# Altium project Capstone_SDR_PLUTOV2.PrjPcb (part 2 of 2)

## Sheet POWERMANAGE.SchDoc
size A3; SheetNumber: 10; SheetTotal: 13; SPICEModelCacheCHAYJENF: <root> / <DocumentId>CHAYJENF</DocumentId> / <CacheFrame Number="0"> / <Model Name="emk105bj105_v-f" Kind="CKT"> / <Text>* EMK105BJ105_V-F     SPICE MODEL  ( General Type ) / *-------------------------------------------------------------------------------------------------------- / * Model Generated by TAIYO YUDEN Corporation (http://www.ty-top.com) / * Version 1.0 / * TAIYO YUDEN Control No. 170508_130520 / * Copyright(c) 2012 TAIYO YUDEN CO.,LTD. All Rights Reserved. / *-------------------------------------------------------------------------------------------------------- / * / * Products Name : Multilayer Ceramic Capacitors / * / * Characteristics : / *     Capacitance : 1 uF , Rated Voltage : 16V , TCC : X5R / *     Case Size : 1.0 x 0.5 / 0.039 x 0.02 [mm/inch] , Thickness : 0.5 / 0.02 [mm/inch] / *     (Conditions: Temperature = 25 degC , DC Bias Current/Voltage = 0A / 0V) / * / * Frequency Range : 40Hz - 3GHz / * / * External Node Assignments : / * / *  1  o---¦ ¦---o  2 / * / *-------------------------------------------------------------------------------------------------------- / .SubCkt EMK105BJ105_V-F 1 2 / **************************** / C0 1 110 0.68309u / Cm 1 101 0.26053u / C1 101 102 0.94076u / Rc1 101 102 1.9029k / C2 102 103 0.66707u / Rc2 102 103 120.36 / C3 103 110 0.57203u / Rc3 103 110 2.1097 / C2m 1 301 0.1871u / C21 301 302 3.2494u / Rc21 301 302 1.1117k / C22 302 303 2.1014u / Rc22 302 303 1.484k / C23 303 304 2.1172u / Rc23 303 304 1.3876k / C24 304 305 0.75729u / Rc24 304 305 332.59 / C25 305 306 0.94401u / Rc25 305 306 249.09 / C26 306 307 0.34674u / Rc26 306 307 28.352 / C27 307 308 0.37158u / Rc27 307 308 19.989 / C28 308 309 0.17933u / Rc28 308 309 31.748 / C29 309 110 0.016445u / Rc29 309 110 1.0592 / Rp0 1 110 100Meg / L0 110 120 0.2216n / Lm 120 130 0.1509n / L1 120 121 0.12659n / RL1 121 130 0.85161 / L2 120 122 0.15996n / RL2 122 130 0.42469 / L3 120 123 7.9543n / RL3 123 130 0.54643m / CR 120 124 0.24334u / LR 124 125 0.090738n / RR 125 130 68.076m / CL 130 140 2.7354p / LL 130 140 0.10762n / RL 130 140 50.614 / Rs 140 2 7.5416m / **************************** / .ends EMK105BJ105_V-F</Text> / </Model> / </CacheFrame> / </root>
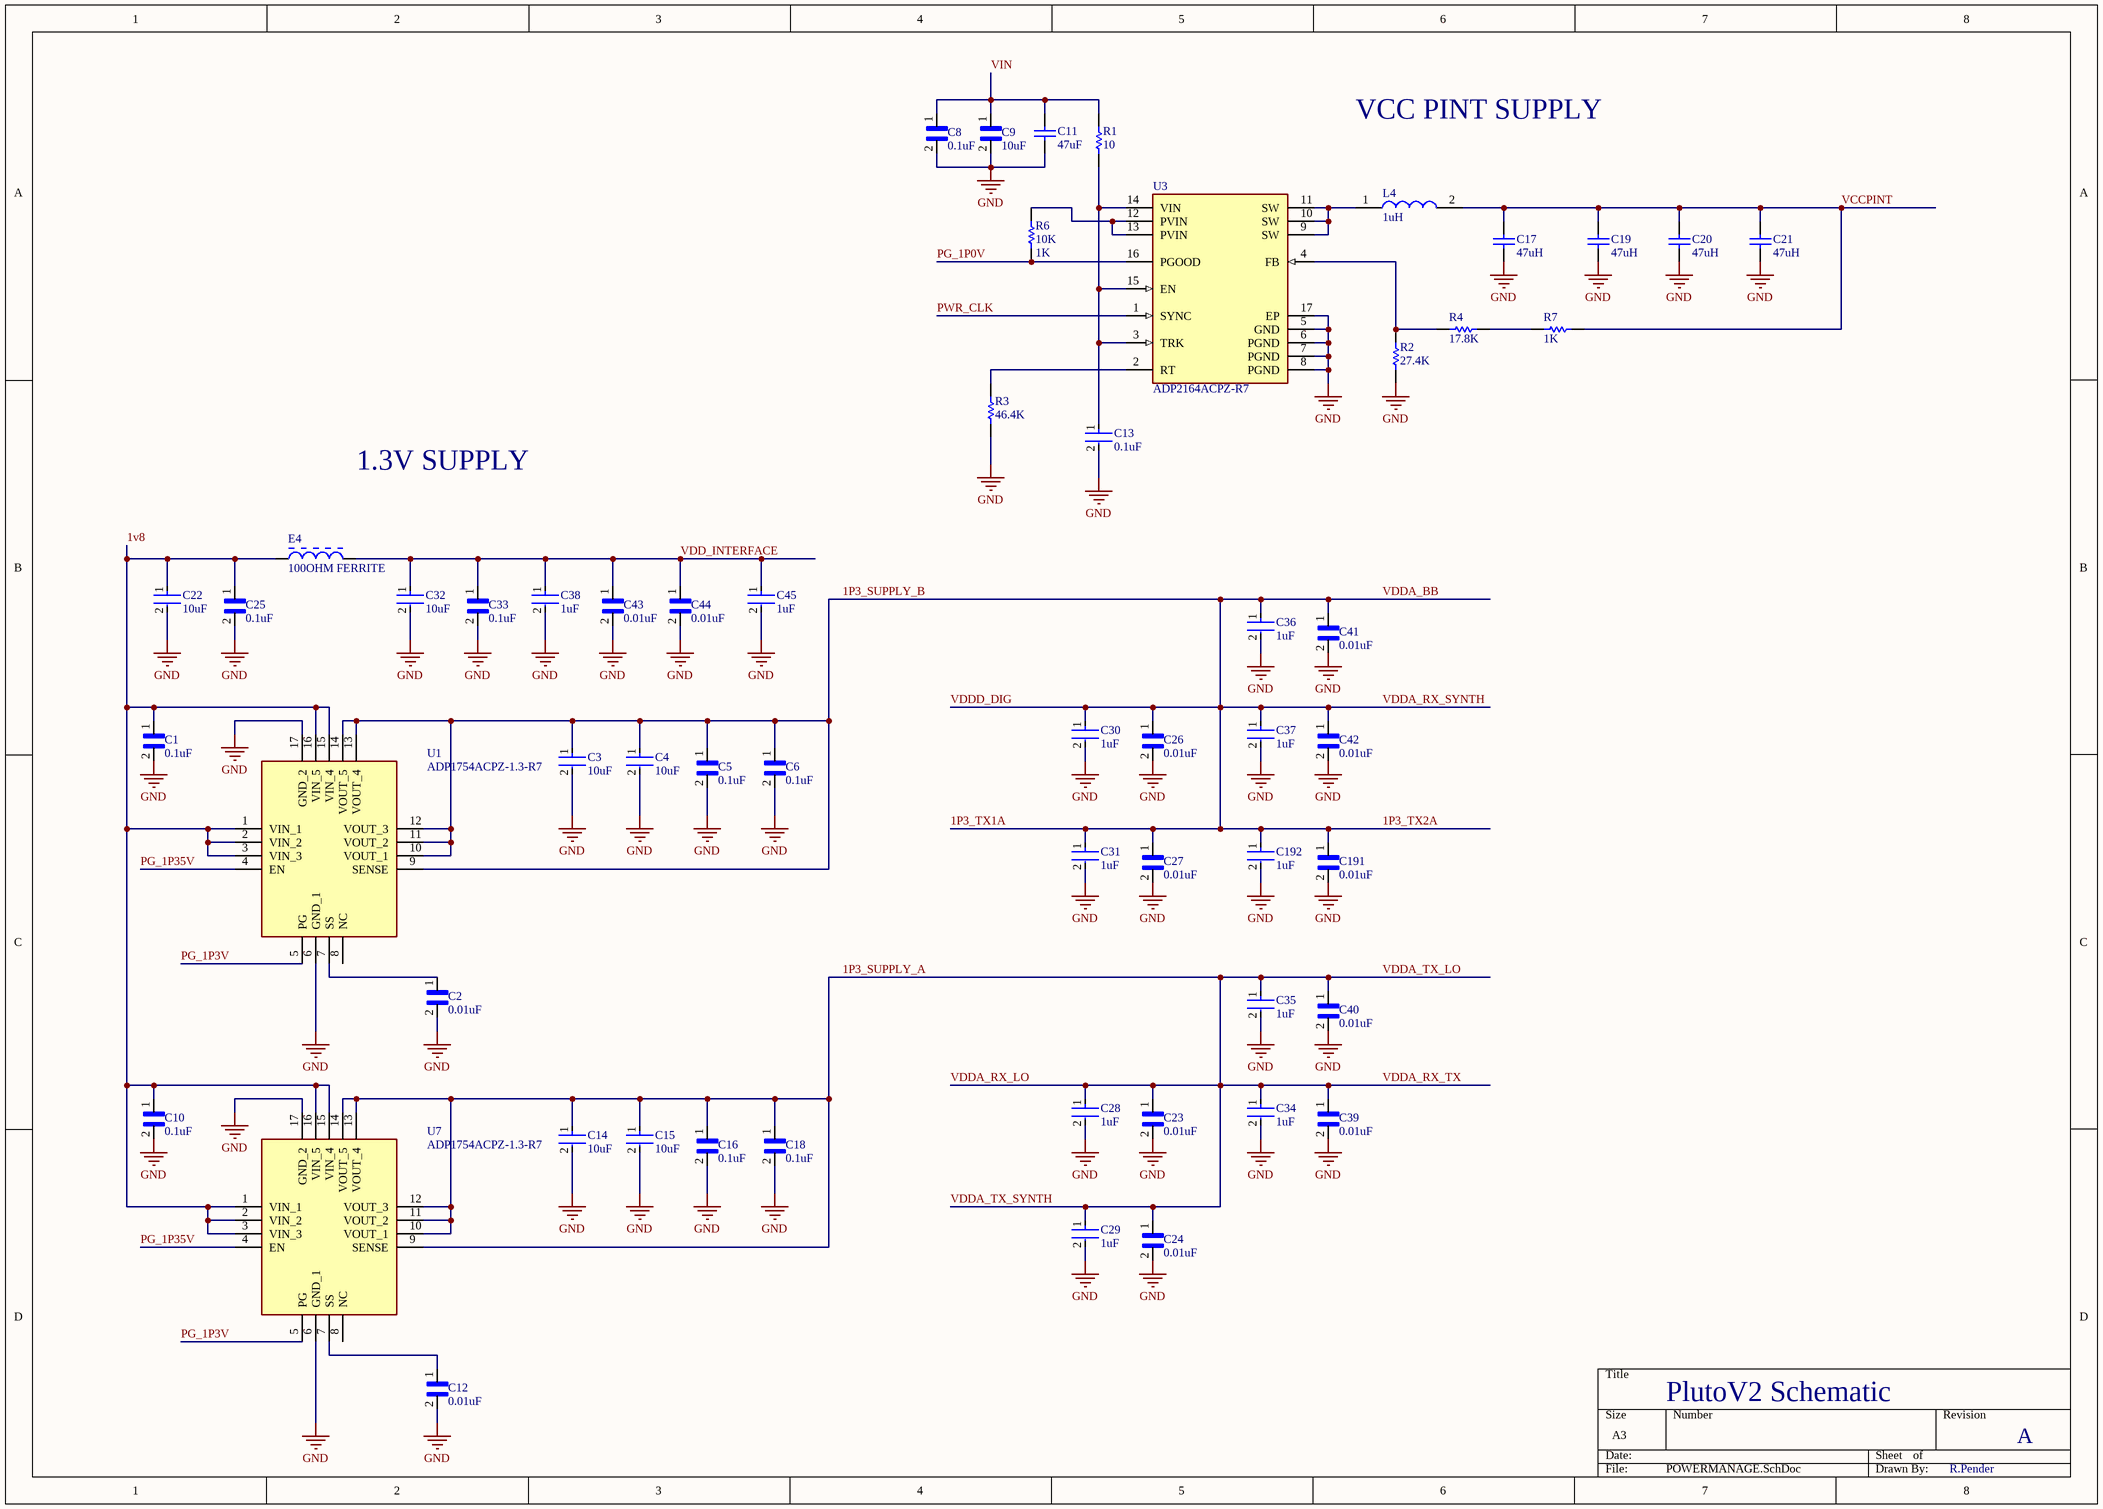
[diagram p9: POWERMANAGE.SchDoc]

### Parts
C1  0.1uF  [CAPC0603X33N]
C2  0.01uF  [CAPC0603X33N]
C3  10uF  [FP-GRM188-0_1-e0_2_0_55-IPC_C]
C4  10uF  [FP-GRM188-0_1-e0_2_0_55-IPC_C]
C5  0.1uF  [CAPC0603X33N]
C6  0.1uF  [CAPC0603X33N]
C8  0.1uF  [CAPC0603X33N]
C9  10uF  [CAPC0603X33N]
C10  0.1uF  [CAPC0603X33N]
C11  47uF  [TAYO-JMK212BBJ476MG-T_L]
C12  0.01uF  [CAPC0603X33N]
C13  0.1uF  [FP-GRM188-0_15-MFG]
C14  10uF  [FP-GRM188-0_1-e0_2_0_55-IPC_C]
C15  10uF  [FP-GRM188-0_1-e0_2_0_55-IPC_C]
C16  0.1uF  [CAPC0603X33N]
C17  47uH  [TAYO-JMK212BBJ476MG-T_L]
C18  0.1uF  [CAPC0603X33N]
C19  47uH  [TAYO-JMK212BBJ476MG-T_L]
C20  47uH  [TAYO-JMK212BBJ476MG-T_L]
C21  47uH  [TAYO-JMK212BBJ476MG-T_L]
C22  10uF  [FP-GRM188-0_1-e0_2_0_55-IPC_C]
C23  0.01uF  [CAPC0603X33N]
C24  0.01uF  [CAPC0603X33N]
C25  0.1uF  [CAPC0603X33N]
C26  0.01uF  [CAPC0603X33N]
C27  0.01uF  [CAPC0603X33N]
C28  1uF  [FP-0402-L_1_0_0_05-W_0_5-IPC_B]
C29  1uF  [FP-0402-L_1_0_0_05-W_0_5-IPC_B]
C30  1uF  [FP-0402-L_1_0_0_05-W_0_5-IPC_B]
C31  1uF  [FP-0402-L_1_0_0_05-W_0_5-IPC_B]
C32  10uF  [FP-GRM188-0_1-e0_2_0_55-IPC_C]
C33  0.1uF  [CAPC0603X33N]
C34  1uF  [FP-0402-L_1_0_0_05-W_0_5-IPC_B]
C35  1uF  [FP-0402-L_1_0_0_05-W_0_5-IPC_B]
C36  1uF  [FP-0402-L_1_0_0_05-W_0_5-IPC_B]
C37  1uF  [FP-0402-L_1_0_0_05-W_0_5-IPC_B]
C38  1uF  [FP-0402-L_1_0_0_05-W_0_5-IPC_A]
C39  0.01uF  [CAPC0603X33N]
C40  0.01uF  [CAPC0603X33N]
C41  0.01uF  [CAPC0603X33N]
C42  0.01uF  [CAPC0603X33N]
C43  0.01uF  [CAPC0603X33N]
C44  0.01uF  [CAPC0603X33N]
C45  1uF  [FP-0402-L_1_0_0_05-W_0_5-IPC_A]
C191  0.01uF  [CAPC0603X33N]
C192  1uF  [FP-0402-L_1_0_0_05-W_0_5-IPC_B]
E4  100OHM FERRITE  [TDK-MPZ2012S101A-2_V]
L4  1uH  [XFL4020102MEB]
R1  10  [RESC0603X26X15LL03T05]
R2  27.4K  [2-0402]
R3  46.4K  [1-0201]
R4  17.8K  [2-0402]
R6  10K  value 1K  [RESC1005X35N]
R7  1K  [2-0402]
U1  ADP1754ACPZ-1.3-R7  [QFN65P400X400X80-17N-D]
U3  ADP2164ACPZ-R7  [FP-CP-16-26-IPC_C]
U7  ADP1754ACPZ-1.3-R7  [QFN65P400X400X80-17N-D]

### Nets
GND: C1.2 C2.2 C3.2 C4.2 C5.2 C6.2 C8.2 C9.2 C10.2 C11.2 C12.2 C13.2 C14.2 C15.2 C16.2 C17.2 C18.2 C19.2 C20.2 C21.2 C22.2 C23.2 C24.2 C25.2 C26.2 C27.2 C28.2 C29.2 C30.2 C31.2 C32.2 C33.2 C34.2 C35.2 C36.2 C37.2 C38.2 C39.2 C40.2 C41.2 C42.2 C43.2 C44.2 C45.2 C191.2 C192.2 R2.2 R3.2 U1.6(GND_1) U1.17(GND_2) U3.5(GND) U3.6(PGND) U3.7(PGND) U3.8(PGND) U3.17(EP) U7.6(GND_1) U7.17(GND_2)
1P3_SUPPLY_A: C14.1 C15.1 C16.1 C18.1 C23.1 C24.1 C28.1 C29.1 C34.1 C35.1 C39.1 C40.1 U7.9(SENSE) U7.10(VOUT_1) U7.11(VOUT_2) U7.12(VOUT_3) U7.13(VOUT_4) U7.14(VOUT_5)  [also labelled VDDA_RX_LO, VDDA_RX_TX, VDDA_TX_LO, VDDA_TX_SYNTH]
1P3_SUPPLY_B: C3.1 C4.1 C5.1 C6.1 C26.1 C27.1 C30.1 C31.1 C36.1 C37.1 C41.1 C42.1 C191.1 C192.1 U1.9(SENSE) U1.10(VOUT_1) U1.11(VOUT_2) U1.12(VOUT_3) U1.13(VOUT_4) U1.14(VOUT_5)  [also labelled 1P3_TX1A, 1P3_TX2A, VDDA_BB, VDDA_RX_SYNTH, VDDD_DIG]
1v8: C1.1 C10.1 C22.1 C25.1 E4.1 U1.1(VIN_1) U1.2(VIN_2) U1.3(VIN_3) U1.15(VIN_4) U1.16(VIN_5) U7.1(VIN_1) U7.2(VIN_2) U7.3(VIN_3) U7.15(VIN_4) U7.16(VIN_5)
PG_1P0V: R6.1 U3.16(PGOOD)
PG_1P3V: U1.5(PG) U7.5(PG)
PG_1P35V: U1.4(EN) U7.4(EN)
PWR_CLK: U3.1(SYNC)
VCCPINT: C17.1 C19.1 C20.1 C21.1 L4.2 R7.2
VDD_INTERFACE: C32.1 C33.1 C38.1 C43.1 C44.1 C45.1 E4.2
VIN: C8.1 C9.1 C11.1 R1.2
NetC2_1: C2.1 U1.7(SS)
NetC12_1: C12.1 U7.7(SS)
NetC13_1: C13.1 R1.1 U3.3(TRK) U3.14(VIN) U3.15(EN)
NetL4_1: L4.1 U3.9(SW) U3.10(SW) U3.11(SW)
NetR2_1: R2.1 R4.1 U3.4(FB)
NetR3_1: R3.1 U3.2(RT)
NetR4_2: R4.2 R7.1
NetR6_2: R6.2 U3.12(PVIN) U3.13(PVIN)

Not connected (* = marked no-connect by the designer): U1 8(NC); U7 8(NC)

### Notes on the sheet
- VCC PINT SUPPLY
- 1.3V SUPPLY
- PlutoV2 Schematic
- A
- R.Pender

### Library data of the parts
C1 C5 C6 C8 C10 C16 C18 C25 C33 = GRM033R61C104ME84D: CAP 0.1UF 16VDC X5R 20% SMD 0201 PAPER TAPE
C2 C9 C12 C23 C24 C26 C27 C39-C44 C191 = GRM033R71A103KA01D: SMD Capacitor X7R(EIA) with Capacitance: 10000pF Tol. 10%. Rated Voltage: 10Vdc; MF: Murata
C3 C4 C14 C15 C22 C32 = CMP-2006-02792-2: Chip Multilayer Ceramic Capacitors for General Purpose, 0603, 10uF, X5R, 15%, 20%, 6.3V
C11 C17 C19-C21 = CMP-2000-06498-1: High Value Multilayer Ceramic Capacitor, 47 uF, +/-20%, 6.3 V, -55 to 85 degC, 2-Pin SMD (0805), RoHS, Tape and Reel; Manufacturer: Taiyo Yuden; PCN Part Number: X5R,X7RDielectrics23/Jan/2008; Kits: 587-1797-KIT-ND-KITCAPCERHICAP0603&0805S; Temperature Coefficient: X5R; Tolerance: ±20%; Online Catalog: MSeries; Other Names: 587-1779-1; Capacitance: 47µF; Voltage - Rated: 6.3V; Catalog Drawings: xMKSeries_0805_1.25
C13 = CMP-06035-003612-1: Chip Multilayer Ceramic Capacitors for General Purpose, 0603, 10uF, X5R, 15%, 20%, 10V
C28-C31 C34-C38 C45 C192 = CMP-14477-000104-2: None; Tolerance: 10%; Voltage Rating: 16V; Dielectric: X5R
E4 = CMP-2000-05399-1: Chip Bead for Power Line, 100 Ohm, +/- 25%, 4 A, -55 to 125 degC, 0805 (2012 Metric), RoHS, Tape and Reel; Manufacturer: TDK; Maximum DC Resistance: 20mOhms; Test Frequency: 100MHz; Impedance: 100Ohms; Case Width: 1.25mm; Case Length: 2mm; Maximum DC Current: 4A; Case Height: 0.85mm
L4 = XFL4020-102MEB: Inductor; Manufacturer_Name: COILCRAFT
R1 = CMP-2004-03448-1: Manufacturer: Panasonic; Part Number: ERJ1GNF10R0C
R2 R4 R7 = ERJ2RK: Precision Thick Film Chip Resistor, 10 Ohm to 1M Ohm Range, 1% and 0.5% Tolerance, 0402 Size, 0.063 W
R3 = ERJ1GE: Thick Film Chip Resistor, 10 Ohm to 1M Ohm Range, 5% Tolerance, 0201 Size, 0.05 W; Note: If flow soldering, adjust pad width of PCB Footprint to 0.7 - 0.8 times the width of the resistor.
R6 = Res1: Resistor
U1 U7 = ADP1754ACPZ-1.3-R7: Integrated Circuit; Manufacturer_Name: Analog Devices
U3 = CMP-09139-000017-1: IC REG BUCK ADJ 4A 16LFCSP; Manufacturer: Analog Devices; Standoff Height: 0.02mm; Max Junction Temp: +125°C; Description: Buck Switching Regulator IC Positive Adjustable 0.6V 1 Output 4A 16-WQFN Exposed Pad, CSP; Max Duty Cycle: 100%; Output Type: AdjustableProgrammable; Switching Frequency: 500-1400kHz; Min Supply Voltage: 2.7V; Max Supply Voltage: 6.5V; Nominal Supply Current: 895uA; Number Of Outputs: 1; Output Voltage: 0.6-6.5V

## Sheet POWERMANAGE2.SchDoc
size A3; SheetNumber: 11; SheetTotal: 13; SPICEModelCacheVRZJBZTH: <root> / <DocumentId>VRZJBZTH</DocumentId> / <CacheFrame Number="0"> / <Model Name="emk105bj105_v-f" Kind="CKT"> / <Text>* EMK105BJ105_V-F     SPICE MODEL  ( General Type ) / *-------------------------------------------------------------------------------------------------------- / * Model Generated by TAIYO YUDEN Corporation (http://www.ty-top.com) / * Version 1.0 / * TAIYO YUDEN Control No. 170508_130520 / * Copyright(c) 2012 TAIYO YUDEN CO.,LTD. All Rights Reserved. / *-------------------------------------------------------------------------------------------------------- / * / * Products Name : Multilayer Ceramic Capacitors / * / * Characteristics : / *     Capacitance : 1 uF , Rated Voltage : 16V , TCC : X5R / *     Case Size : 1.0 x 0.5 / 0.039 x 0.02 [mm/inch] , Thickness : 0.5 / 0.02 [mm/inch] / *     (Conditions: Temperature = 25 degC , DC Bias Current/Voltage = 0A / 0V) / * / * Frequency Range : 40Hz - 3GHz / * / * External Node Assignments : / * / *  1  o---¦ ¦---o  2 / * / *-------------------------------------------------------------------------------------------------------- / .SubCkt EMK105BJ105_V-F 1 2 / **************************** / C0 1 110 0.68309u / Cm 1 101 0.26053u / C1 101 102 0.94076u / Rc1 101 102 1.9029k / C2 102 103 0.66707u / Rc2 102 103 120.36 / C3 103 110 0.57203u / Rc3 103 110 2.1097 / C2m 1 301 0.1871u / C21 301 302 3.2494u / Rc21 301 302 1.1117k / C22 302 303 2.1014u / Rc22 302 303 1.484k / C23 303 304 2.1172u / Rc23 303 304 1.3876k / C24 304 305 0.75729u / Rc24 304 305 332.59 / C25 305 306 0.94401u / Rc25 305 306 249.09 / C26 306 307 0.34674u / Rc26 306 307 28.352 / C27 307 308 0.37158u / Rc27 307 308 19.989 / C28 308 309 0.17933u / Rc28 308 309 31.748 / C29 309 110 0.016445u / Rc29 309 110 1.0592 / Rp0 1 110 100Meg / L0 110 120 0.2216n / Lm 120 130 0.1509n / L1 120 121 0.12659n / RL1 121 130 0.85161 / L2 120 122 0.15996n / RL2 122 130 0.42469 / L3 120 123 7.9543n / RL3 123 130 0.54643m / CR 120 124 0.24334u / LR 124 125 0.090738n / RR 125 130 68.076m / CL 130 140 2.7354p / LL 130 140 0.10762n / RL 130 140 50.614 / Rs 140 2 7.5416m / **************************** / .ends EMK105BJ105_V-F</Text> / </Model> / </CacheFrame> / </root>
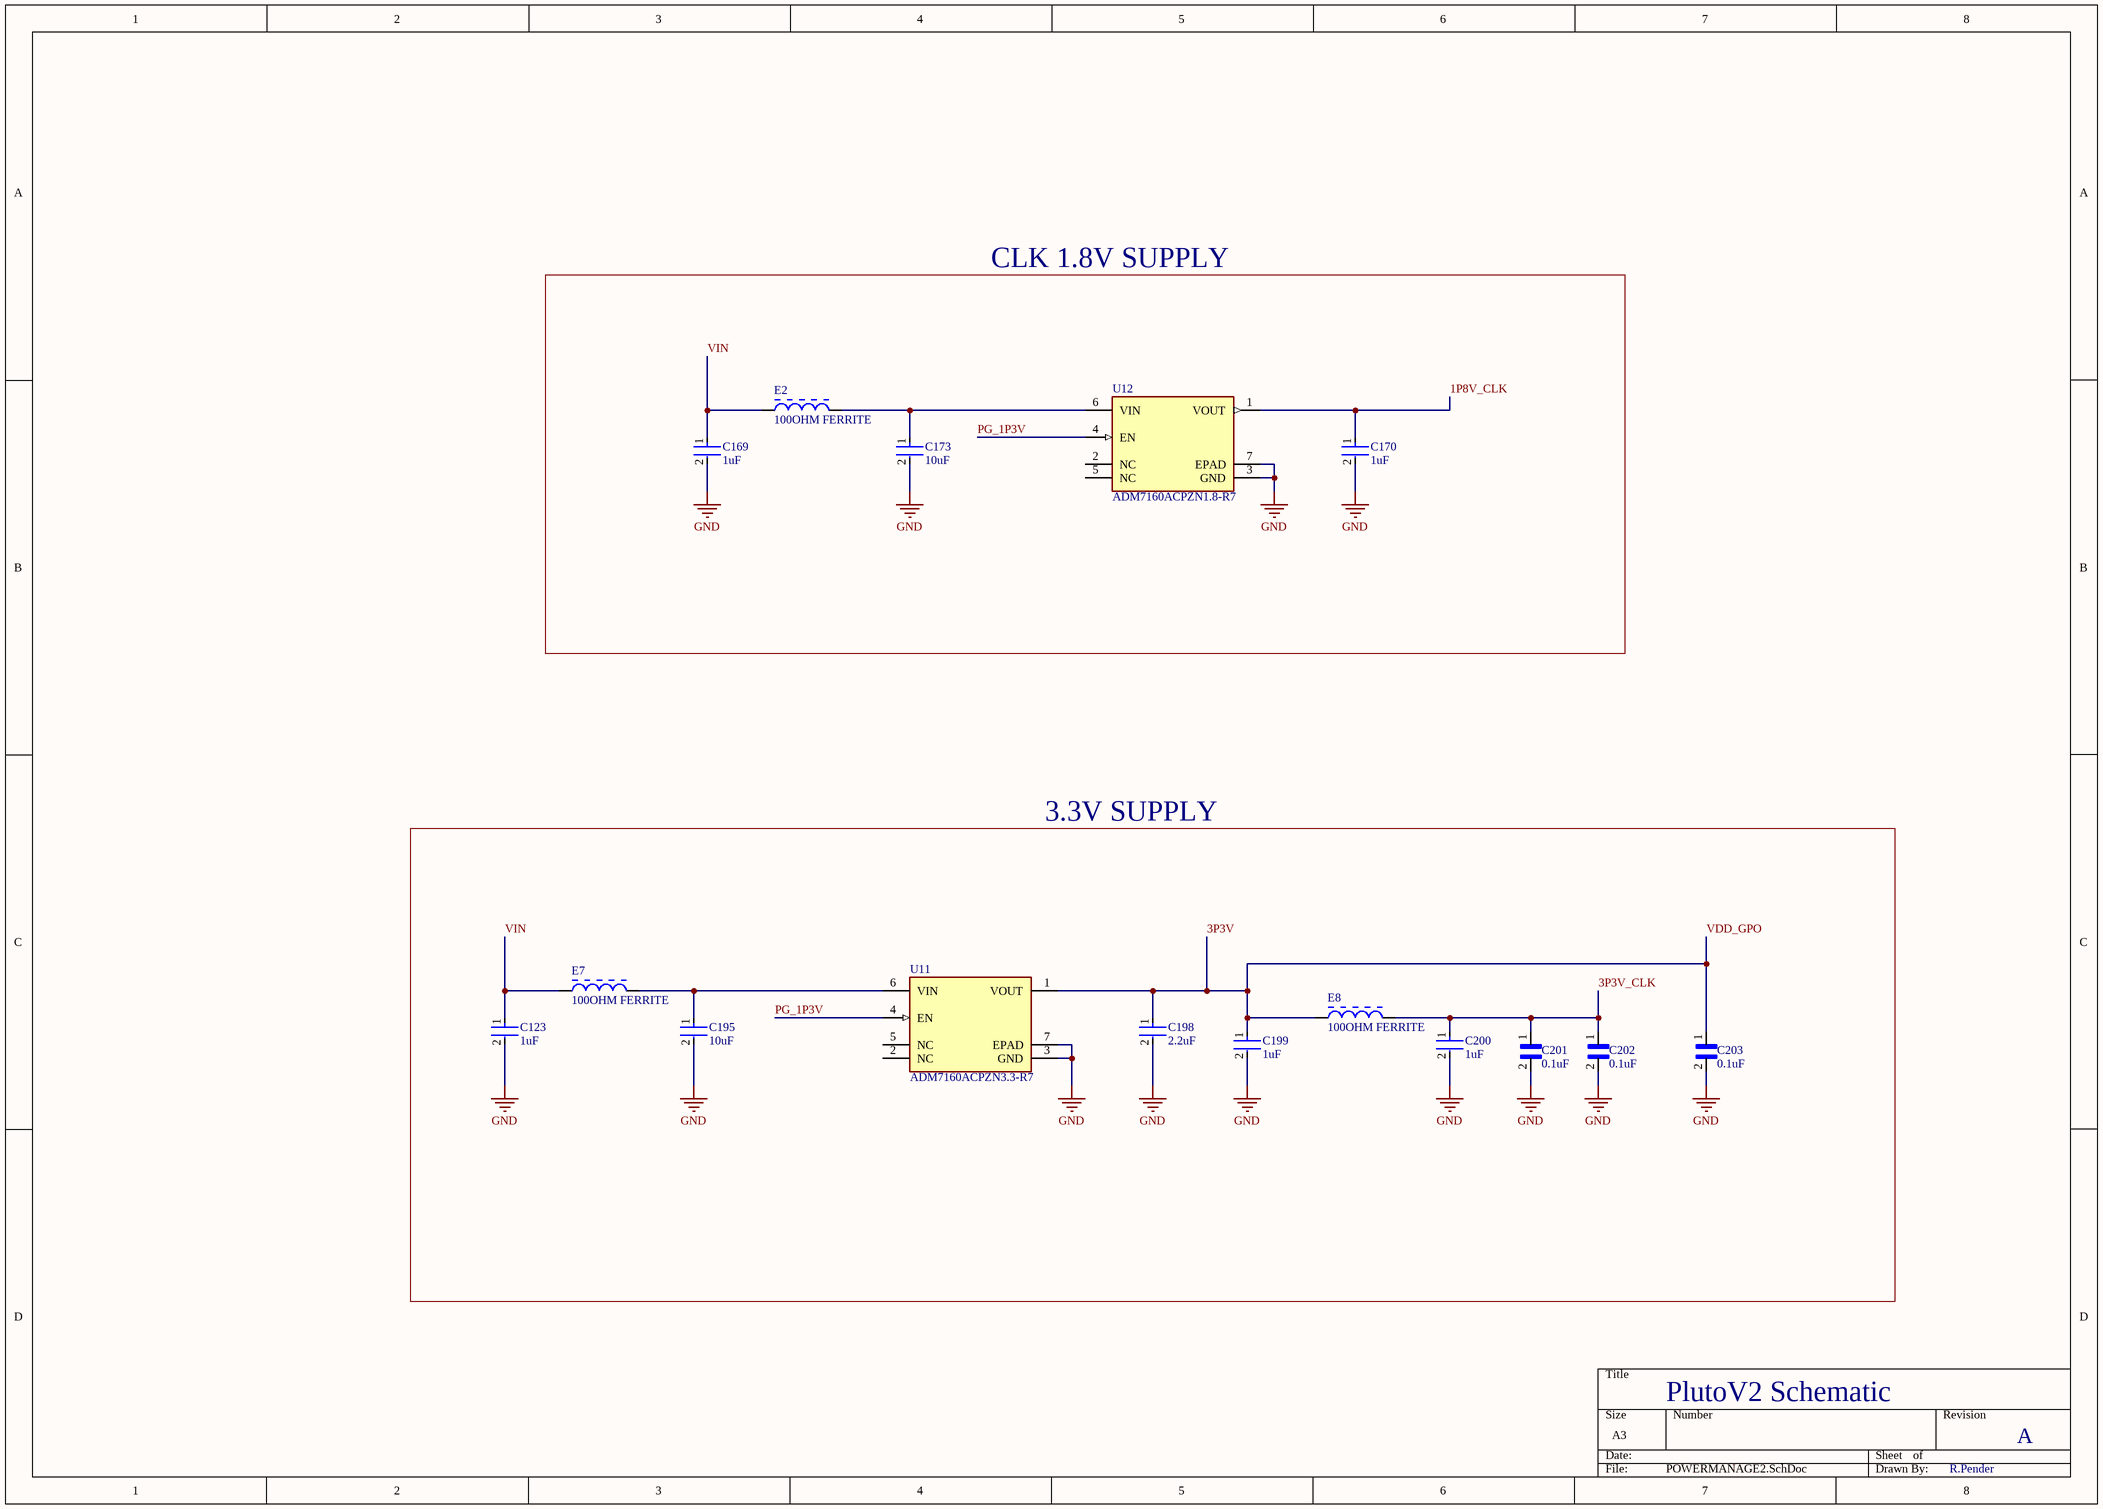
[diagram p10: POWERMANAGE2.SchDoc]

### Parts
C123  1uF  [FP-0402-L_1_0_0_05-W_0_5-IPC_A]
C169  1uF  [FP-0402-L_1_0_0_05-W_0_5-IPC_A]
C170  1uF  [FP-0402-L_1_0_0_05-W_0_5-IPC_B]
C173  10uF  [FP-GRM188-0_15-MFG]
C195  10uF  [FP-GRM188-0_15-MFG]
C198  2.2uF  [FP-GRM188-0_2-MFG]
C199  1uF  [FP-0402-L_1_0_0_05-W_0_5-IPC_A]
C200  1uF  [FP-0402-L_1_0_0_05-W_0_5-IPC_A]
C201  0.1uF  [CAPC0603X33N]
C202  0.1uF  [CAPC0603X33N]
C203  0.1uF  [CAPC0603X33N]
E2  100OHM FERRITE  [TDK-MPZ2012S101A-2_V]
E7  100OHM FERRITE  [TDK-MPZ2012S101A-2_V]
E8  100OHM FERRITE  [TDK-MPZ2012S101A-2_V]
U11  ADM7160ACPZN3.3-R7  [FP-CP-6-3-IPC_A]
U12  ADM7160ACPZN1.8-R7  [FP-CP-6-3-IPC_C]

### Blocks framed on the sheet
CLK 1.8V SUPPLY: C169 C170 C173 E2 U12
3.3V SUPPLY: C123 C195 C198-C203 E7 E8 U11

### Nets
GND: C123.2 C169.2 C170.2 C173.2 C195.2 C198.2 C199.2 C200.2 C201.2 C202.2 C203.2 U11.3(GND) U11.7(EPAD) U12.3(GND) U12.7(EPAD)
1P8V_CLK: C170.1 U12.1(VOUT)
3P3V: C198.1 C199.1 C203.1 E8.1 U11.1(VOUT)  [also labelled VDD_GPO]
3P3V_CLK: C200.1 C201.1 C202.1 E8.2
PG_1P3V: U11.4(EN) U12.4(EN)
VIN: C123.1 C169.1 E2.1 E7.1
NetC173_1: C173.1 E2.2 U12.6(VIN)
NetC195_1: C195.1 E7.2 U11.6(VIN)

Not connected (* = marked no-connect by the designer): U11 2(NC) 5(NC); U12 2(NC) 5(NC)

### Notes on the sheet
- PlutoV2 Schematic
- A
- R.Pender

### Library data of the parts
C123 C169 C170 C199 C200 = CMP-14477-000104-2: as C28-C31 on sheet POWERMANAGE
C173 C195 = CMP-06035-003612-1: as C13 on sheet POWERMANAGE
C198 = CMP-06035-023692-1: Chip Multilayer Ceramic Capacitors for General Purpose, 0603, 2.2uF, X5R, 15%, 10%, 50V
C201-C203 = GRM033R61C104ME84D: as C1 on sheet POWERMANAGE
E2 E7 E8 = CMP-2000-05399-1: as E4 on sheet POWERMANAGE
U11 = CMP-09138-000129-1: IC REG LINEAR 3.3V 200MA 6LFCSP; Output Type: Fixed; Max Supply Current: 265uA; Max Input Voltage: 5.5V; Number of Regulators: 1; Power Supply Rejection Ratio (PSRR): 49dB; Operating Supply Current: 265mA; Polarity: Positive; Min Input Voltage: 2.2V; Dropout Voltage: 150mV; Accuracy: 1%; Min Current Limit: 220mA
U12 = CMP-09138-000112-1: IC REG LINEAR 1.8V 200MA 6LFCSP; Operating Supply Current: 265mA; Power Supply Rejection Ratio (PSRR): 49dB; Polarity: Positive; Max Supply Current: 265uA; Dropout Voltage: 230mV; Number of Outputs: 1; Min Current Limit: 220mA; Output Type: Fixed; Accuracy: 1%; Min Input Voltage: 2.2V; Max Input Voltage: 5.5V

## Sheet TESTPOINTS.SchDoc
size A3; SheetNumber: 12; SheetTotal: 13
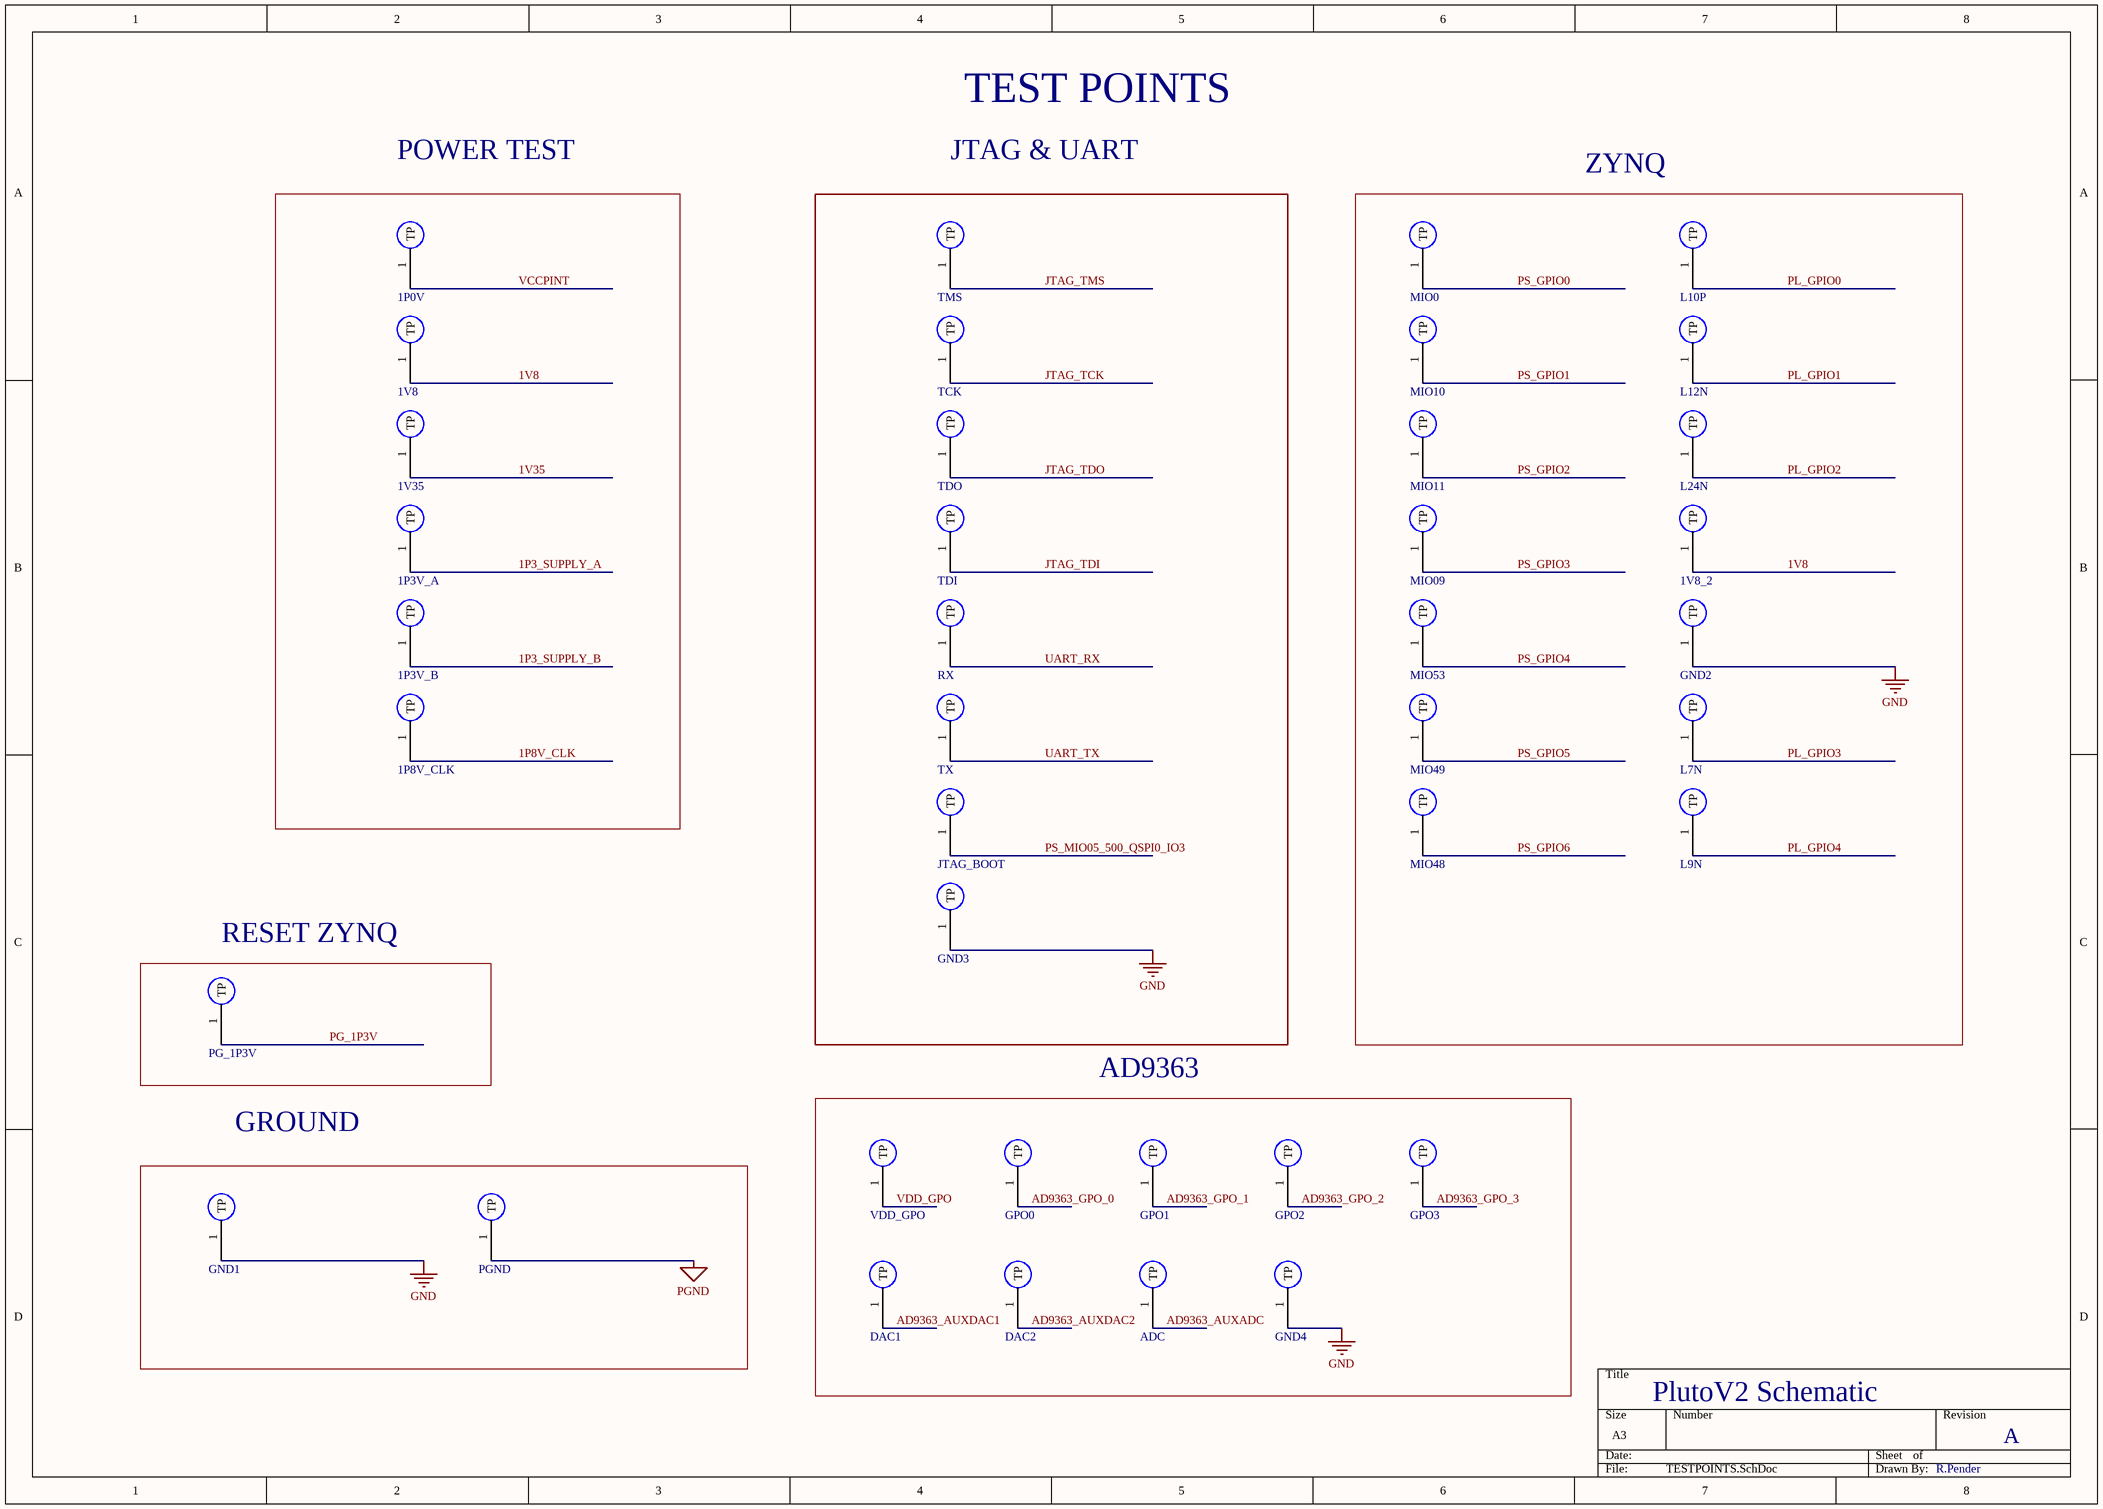
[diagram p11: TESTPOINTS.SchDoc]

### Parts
1P0V  TEST POINT  [TESTPOINT1]  (value not drawn)  (no BOM)
1P3V_A  TEST POINT  [TESTPOINT1]  (value not drawn)  (no BOM)
1P3V_B  TEST POINT  [TESTPOINT1]  (value not drawn)  (no BOM)
1P8V_CLK  TEST POINT  [TESTPOINT1]  (value not drawn)  (no BOM)
1V8  TEST POINT  [TESTPOINT1]  (value not drawn)  (no BOM)
1V8_2  TEST POINT  [TESTPOINT1]  (value not drawn)  (no BOM)
1V35  TEST POINT  [TESTPOINT1]  (value not drawn)  (no BOM)
ADC  TEST POINT  [TESTPOINT1]  (value not drawn)  (no BOM)
DAC1  TEST POINT  [TESTPOINT1]  (value not drawn)  (no BOM)
DAC2  TEST POINT  [TESTPOINT1]  (value not drawn)  (no BOM)
GND1  TEST POINT  [TESTPOINT1]  (value not drawn)  (no BOM)
GND2  TEST POINT  [TESTPOINT1]  (value not drawn)  (no BOM)
GND3  TEST POINT  [TESTPOINT1]  (value not drawn)  (no BOM)
GND4  TEST POINT  [TESTPOINT1]  (value not drawn)  (no BOM)
GPO0  TEST POINT  [TESTPOINT1]  (value not drawn)  (no BOM)
GPO1  TEST POINT  [TESTPOINT1]  (value not drawn)  (no BOM)
GPO2  TEST POINT  [TESTPOINT1]  (value not drawn)  (no BOM)
GPO3  TEST POINT  [TESTPOINT1]  (value not drawn)  (no BOM)
JTAG_BOOT  TEST POINT  [TESTPOINT1]  (value not drawn)  (no BOM)
L7N  TEST POINT  [TESTPOINT1]  (value not drawn)  (no BOM)
L9N  TEST POINT  [TESTPOINT1]  (value not drawn)  (no BOM)
L10P  TEST POINT  [TESTPOINT1]  (value not drawn)  (no BOM)
L12N  TEST POINT  [TESTPOINT1]  (value not drawn)  (no BOM)
L24N  TEST POINT  [TESTPOINT1]  (value not drawn)  (no BOM)
MIO0  TEST POINT  [TESTPOINT1]  (value not drawn)  (no BOM)
MIO09  TEST POINT  [TESTPOINT1]  (value not drawn)  (no BOM)
MIO10  TEST POINT  [TESTPOINT1]  (value not drawn)  (no BOM)
MIO11  TEST POINT  [TESTPOINT1]  (value not drawn)  (no BOM)
MIO48  TEST POINT  [TESTPOINT1]  (value not drawn)  (no BOM)
MIO49  TEST POINT  [TESTPOINT1]  (value not drawn)  (no BOM)
MIO53  TEST POINT  [TESTPOINT1]  (value not drawn)  (no BOM)
PG_1P3V  TEST POINT  [TESTPOINT1]  (value not drawn)  (no BOM)
PGND  TEST POINT  [TESTPOINT1]  (value not drawn)  (no BOM)
RX  TEST POINT  [TESTPOINT1]  (value not drawn)  (no BOM)
TCK  TEST POINT  [TESTPOINT1]  (value not drawn)  (no BOM)
TDI  TEST POINT  [TESTPOINT1]  (value not drawn)  (no BOM)
TDO  TEST POINT  [TESTPOINT1]  (value not drawn)  (no BOM)
TMS  TEST POINT  [TESTPOINT1]  (value not drawn)  (no BOM)
TX  TEST POINT  [TESTPOINT1]  (value not drawn)  (no BOM)
VDD_GPO  TEST POINT  [TESTPOINT1]  (value not drawn)  (no BOM)

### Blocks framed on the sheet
ZYNQ: 1V8_2 GND2 L7N L9N L10P L12N L24N MIO0 MIO09-MIO11 MIO48 MIO49 MIO53
RESET ZYNQ: PG_1P3V
AD9363: ADC DAC1 DAC2 GND4 GPO0-GPO3 VDD_GPO

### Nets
GND: GND1.1(TP) GND2.1(TP) GND3.1(TP) GND4.1(TP)
PGND: PGND.1(TP)
1P3_SUPPLY_A: 1P3V_A.1(TP)
1P3_SUPPLY_B: 1P3V_B.1(TP)
1P8V_CLK: 1P8V_CLK.1(TP)
1v8: 1V8.1(TP) 1V8_2.1(TP)
1v35: 1V35.1(TP)
AD9363_AUXADC: ADC.1(TP)
AD9363_AUXDAC1: DAC1.1(TP)
AD9363_AUXDAC2: DAC2.1(TP)
AD9363_GPO_0: GPO0.1(TP)
AD9363_GPO_1: GPO1.1(TP)
AD9363_GPO_2: GPO2.1(TP)
AD9363_GPO_3: GPO3.1(TP)
JTAG_TCK: TCK.1(TP)
JTAG_TDI: TDI.1(TP)
JTAG_TDO: TDO.1(TP)
JTAG_TMS: TMS.1(TP)
PG_1P3V: PG_1P3V.1(TP)
PL_GPIO0: L10P.1(TP)
PL_GPIO1: L12N.1(TP)
PL_GPIO2: L24N.1(TP)
PL_GPIO3: L7N.1(TP)
PL_GPIO4: L9N.1(TP)
PS_GPIO0: MIO0.1(TP)
PS_GPIO1: MIO10.1(TP)
PS_GPIO2: MIO11.1(TP)
PS_GPIO3: MIO09.1(TP)
PS_GPIO4: MIO53.1(TP)
PS_GPIO5: MIO49.1(TP)
PS_GPIO6: MIO48.1(TP)
PS_MIO05_500_QSPI0_IO3: JTAG_BOOT.1(TP)
UART_RX: RX.1(TP)
UART_TX: TX.1(TP)
VCCPINT: 1P0V.1(TP)
VDD_GPO: VDD_GPO.1(TP)  [project net 3P3V]

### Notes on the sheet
- TEST POINTS
- POWER TEST
- JTAG & UART
- GROUND
- PlutoV2 Schematic
- A
- R.Pender

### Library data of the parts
1P0V 1P3V_A 1P3V_B 1P8V_CLK 1V8 1V8_2 1V35 ADC DAC1 DAC2 GND1-GND4 GPO0-GPO3 JTAG_BOOT L7N L9N L10P L12N L24N MIO0 MIO09-MIO11 MIO48 MIO49 MIO53 PG_1P3V PGND RX TCK TDI TDO TMS TX VDD_GPO = TESTPT

## Sheet AD9363 OSCILLATORS.SchDoc
size A3; SheetNumber: 13; SheetTotal: 13
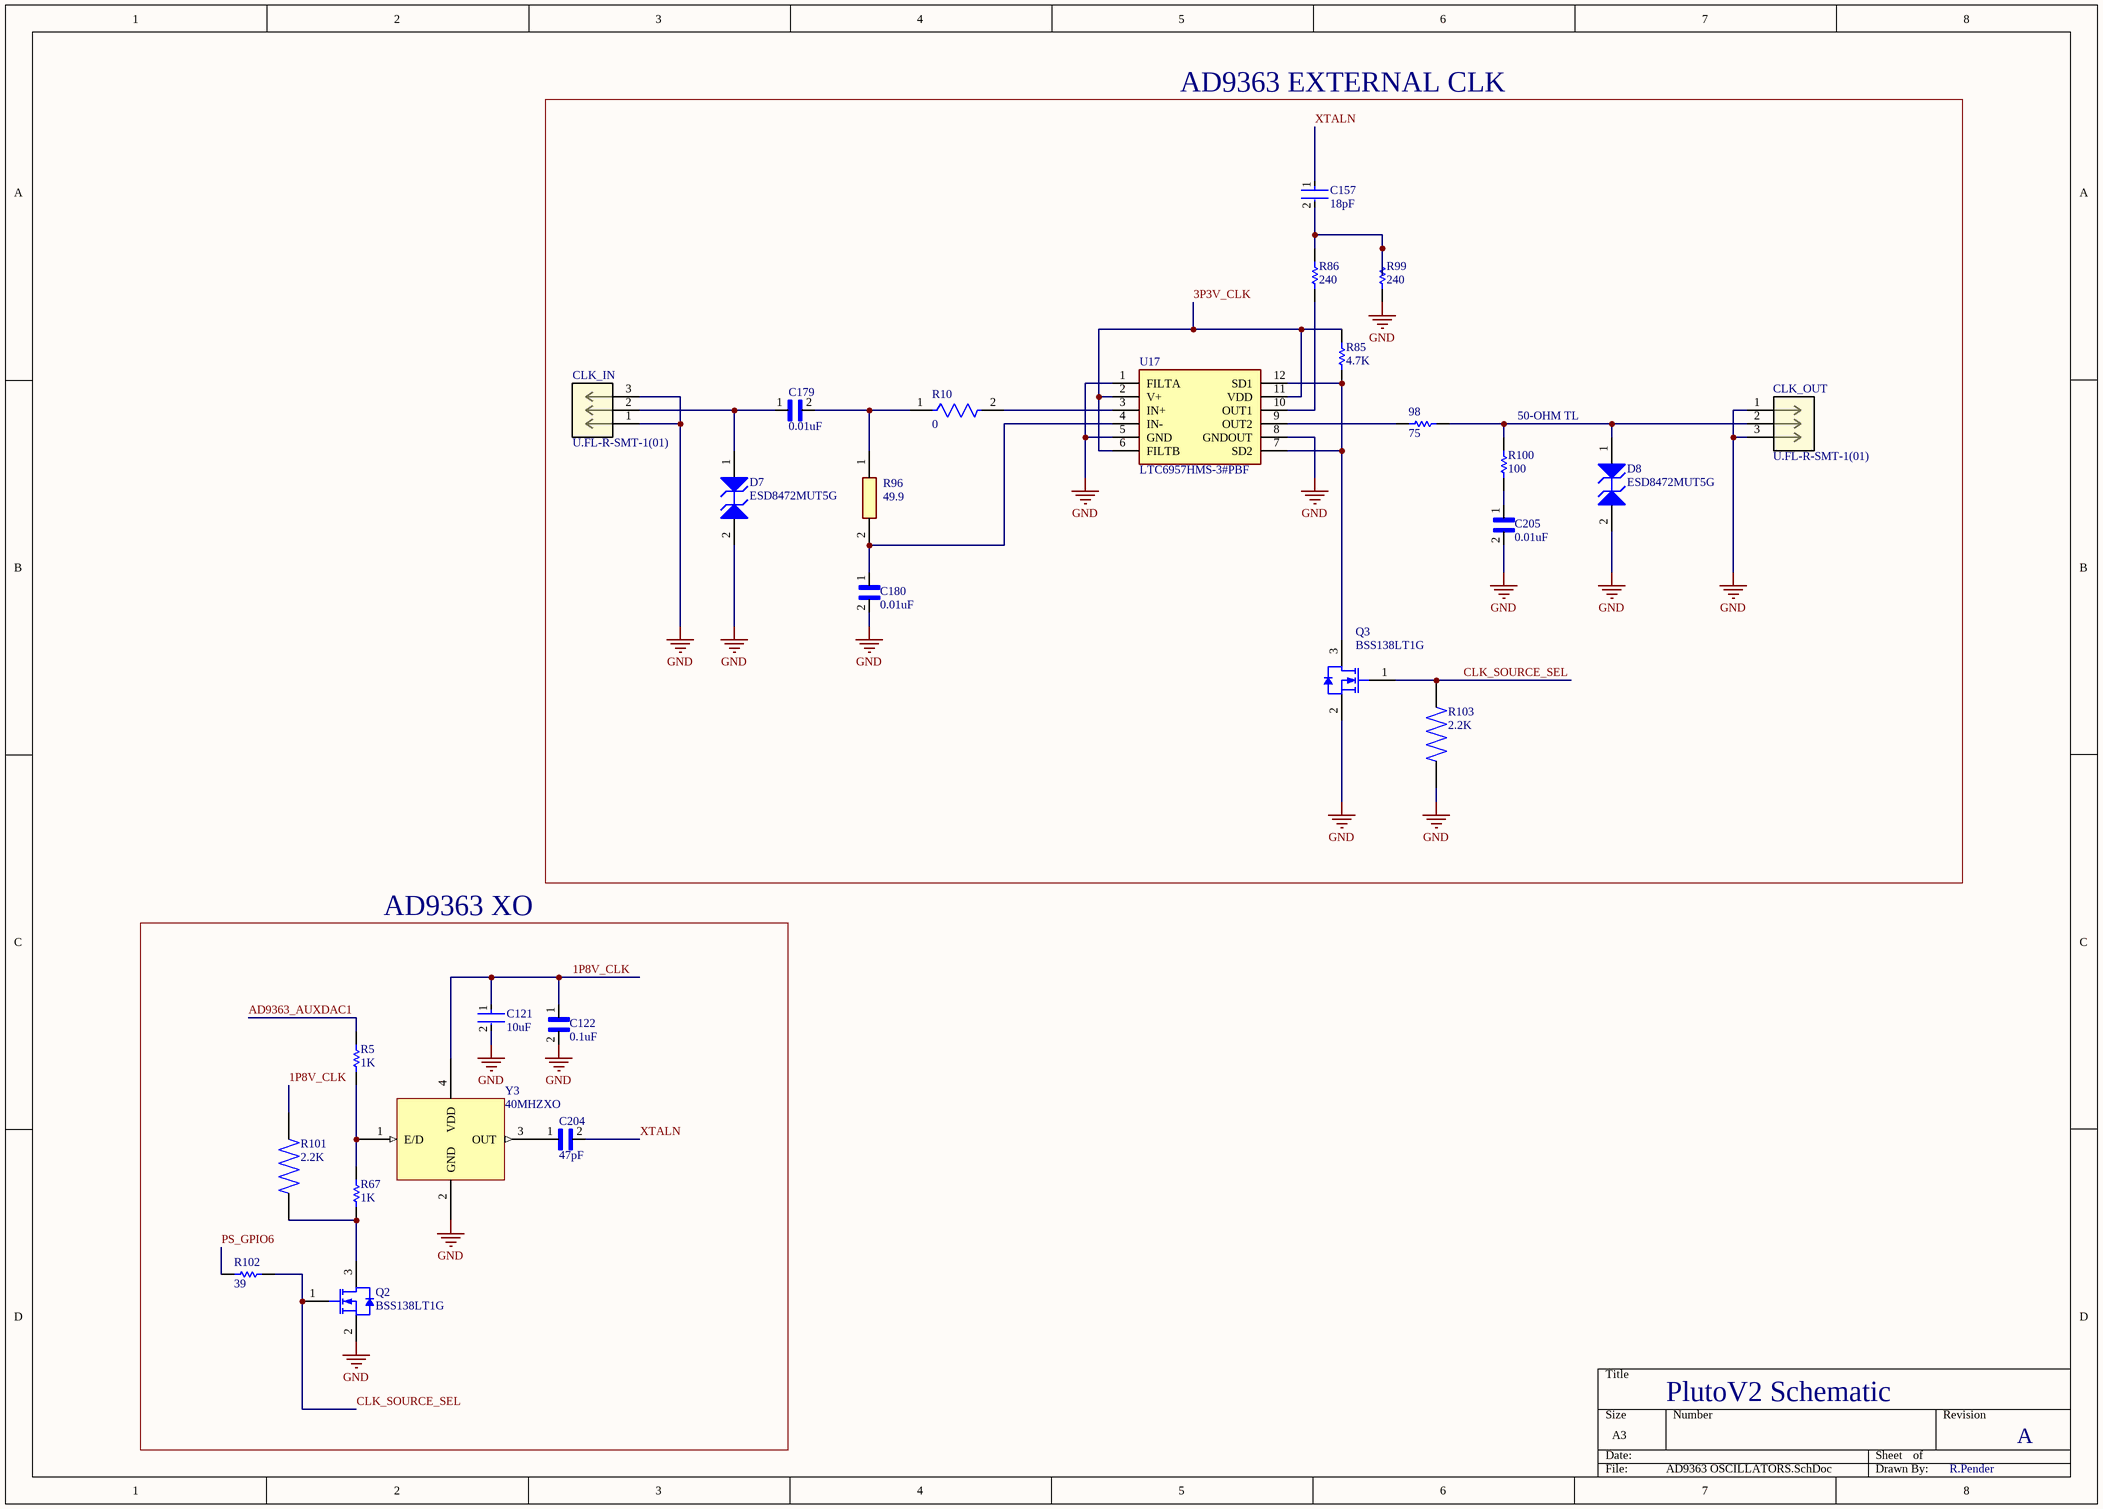
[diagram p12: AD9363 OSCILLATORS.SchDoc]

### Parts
98  75  [2-0402]
C121  10uF  [FP-GRM188-0_1-e0_2_0_55-IPC_C]
C122  0.1uF  [CAPC0603X33N]
C157  18pF  [FP-GRM033-0_03-IPC_A]
C179  0.01uF  [CAPC0603X33N]
C180  0.01uF  [CAPC0603X33N]
C204  47pF  [CAPC1005X55N]
C205  0.01uF  [CAPC0603X33N]
CLK_IN  U.FL-R-SMT-1(01)  [CONN_-SMT-1(01)]
CLK_OUT  U.FL-R-SMT-1(01)  [CONN_-SMT-1(01)]
D7  ESD8472MUT5G  [ONSC-X3DFN-2-152AF-01_V]
D8  ESD8472MUT5G  [ONSC-X3DFN-2-152AF-01_V]
Q2  BSS138LT1G  [ONSC-SOT-23-3-318-08_V]
Q3  BSS138LT1G  [ONSC-SOT-23-3-318-08_V]
R5  1K  [RESC0603X26X15NL03T05]
R10  0  [FP-ERJ1GN-IPC_A]
R67  1K  [2-0402]
R85  4.7K  [2-0402]
R86  240  [2-0402]
R96  49.9  [RESC1608X46N]
R99  240  [2-0402]
R100  100  [2-0402]
R101  2.2K  [RESC1005X35N]
R102  39  [2-0402]
R103  2.2K  [RESC1005X35N]
U17  LTC6957HMS-3#PBF  [SOP65P490X110-12N]
Y3  40MHZXO

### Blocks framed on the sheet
AD9363 EXTERNAL CLK: 98 C157 C179 C180 C205 CLK_IN CLK_OUT D7 D8 Q3 R10 R85 R86 R96 R99 R100 R103 U17
AD9363 XO: C121 C122 C204 Q2 R5 R67 R101 R102 Y3

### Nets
GND: C121.2 C122.2 C180.2 C205.2 CLK_IN.1 CLK_IN.3 CLK_OUT.1 CLK_OUT.3 D7.2(A2) D8.2(A2) Q2.2(S) Q3.2(S) R99.1 R103.2 U17.1(FILTA) U17.5(GND) U17.8(GNDOUT) Y3.2(GND)
1P8V_CLK: C121.1 C122.1 R101.2 Y3.4(VDD)
3P3V_CLK: R85.2 U17.2(V+) U17.6(FILTB) U17.11(VDD)
AD9363_AUXDAC1: R5.1
CLK_SOURCE_SEL: Q2.1(G) Q3.1(G) R102.2 R103.1
PS_GPIO6: R102.1
XTALN: C157.1 C204.2
Net98_1: 98.1 U17.9(OUT2)
Net98_2: 98.2 CLK_OUT.2 D8.1(A1) R100.1
NetC157_2: C157.2 R86.2 R99.2
NetC179_1: C179.1 CLK_IN.2 D7.1(A1)
NetC179_2: C179.2 R10.1 R96.1
NetC180_1: C180.1 R96.2 U17.4(IN-)
NetC204_1: C204.1 Y3.3(OUT)
NetC205_1: C205.1 R100.2
NetQ2_3: Q2.3(D) R67.2 R101.1
NetQ3_3: Q3.3(D) R85.1 U17.7(SD2) U17.12(SD1)
NetR5_2: R5.2 R67.1 Y3.1(E/D)
NetR10_2: R10.2 U17.3(IN+)
NetR86_1: R86.1 U17.10(OUT1)

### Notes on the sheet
- (near R100) 50-OHM TL
- PlutoV2 Schematic
- A
- R.Pender

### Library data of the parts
98 R67 R85 R86 R99 R100 = ERJ2RK: as R2 on sheet POWERMANAGE
C121 = CMP-2006-02792-2: as C3 on sheet POWERMANAGE
C122 = GRM033R61C104ME84D: as C1 on sheet POWERMANAGE
C157 = CMP-2010-01507-2: Chip Multilayer Ceramic Capacitors for General Purpose, 0201, 18pF, C0G, 30ppm/°C, 5%, 50V
C179 C180 C205 = GRM033R71A103KA01D: as C2 on sheet POWERMANAGE
C204 = GCM1555C1H470JA16D: 47pF Â±5% 50V Ceramic Capacitor C0G, NP0 0402 (1005 Metric); MF: Murata
CLK_IN CLK_OUT = U.FL-R-SMT-1(01): No Description Available; Mfr_Name: Hirose
D7 D8 = CMP-1063-00281-1: Ultra-Low Capacitance ESD Protection, Micro-Packaged Diode for ESD Protection, 2-Pin X3DFN, Pb-Free, Tape and Reel; Manufacturer: On Semiconductor; IR Max (uA): 0.05; C Max (pF): 0.3; V(BR) Min (V): 7; VRWM Max (V): 5.3; Number of Lines: 1; Direction: Bidirectional
Q2 Q3 = CMP-1058-00767-1: Power MOSFET, 200 mA, 50 V, N-Channel, 3-Pin SOT-23, Pb-Free, Tape and Reel; Manufacturer: On Semiconductor; PD Max (W): 0.225; Coss Typ (pF): 12; V(BR)DSS Min (V): 50; VGS Max (V): 20; Channel Polarity: N Channel; Configuration: Single; VGS(th) Max (V): 1.5; Ciss Typ (pF): 40; Crss Typ (pF): 3.5; ID Max (A): 0.2
R5 = CMP-2004-03448-1: as R1 on sheet POWERMANAGE
R10 = CMP-1010-00001-3: RES SMD 0 OHM JUMPER 1/20W 0201; Temperature Coefficient: 600ppm/°C; Max Power Dissipation: 50mW; Resistance: 0R; Voltage Rating: 25V; Tolerance: 1%
R96 = PCAN0603E49R9BST5: Resistor; Manufacturer_Name: Vishay
R101 R103 = CRCW04022K20FKEDC: 2.2 kOhms Â±1% 0.063W, 1/16W Chip Resistor 0402 _1005 Metric_ Thick Film; MF: Vishay
R102 = ERJ2GE: Thick Film Chip Resistor, 1 Ohm to 2.2M Ohm Range, 5% Tolerance, 0402 Size, 0.063 W; Note: If flow soldering, adjust pad width of PCB Footprint to 0.7 - 0.8 times the width of the resistor.
U17 = LTC6957HMS-3#PBF: Integrated Circuit; Manufacturer_Name: Analog Devices

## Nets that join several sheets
GND: USB (28 pins), DDR3 (48 pins), ZYNQ JTAG and Decoupling (70 pins), ZYNQ 34_35 and QPSI (23 pins), AD9363 (56 pins), RF FRONTEND (24 pins), CONNECTORS_SELECTORS (25 pins), POWERREG (29 pins), POWERMANAGE (57 pins), POWERMANAGE2 (15 pins), TESTPOINTS (GND1.1 GND2.1 GND3.1 GND4.1), AD9363 OSCILLATORS (18 pins)
PGND: CONNECTORS_SELECTORS (8 pins), TESTPOINTS (PGND.1)
1P3_SUPPLY_A: AD9363 (6 pins), POWERMANAGE (18 pins), TESTPOINTS (1P3V_A.1)
1P3_SUPPLY_B: AD9363 (7 pins), RF FRONTEND (10 pins), POWERMANAGE (20 pins), TESTPOINTS (1P3V_B.1)
1P8V_CLK: POWERMANAGE2 (C170.1 U12.1), TESTPOINTS (1P8V_CLK.1), AD9363 OSCILLATORS (C121.1 C122.1 R101.2 Y3.4)
1v8: USB (24 pins), DDR3 (C82.1 C83.1 R44.1), ZYNQ JTAG and Decoupling (36 pins), ZYNQ 34_35 and QPSI (23 pins), CONNECTORS_SELECTORS (P1.10), POWERREG (5 pins), POWERMANAGE (15 pins), TESTPOINTS (1V8.1 1V8_2.1)
1v35: DDR3 (31 pins), ZYNQ JTAG and Decoupling (14 pins), POWERREG (5 pins), TESTPOINTS (1V35.1)
3P3V: AD9363 (U5.B8), POWERMANAGE2 (5 pins), TESTPOINTS (VDD_GPO.1)
3P3V_CLK: POWERMANAGE2 (C200.1 C201.1 C202.1 E8.2), AD9363 OSCILLATORS (R85.2 U17.2 U17.6 U17.11)
AD9363_AUXADC: AD9363 (C207.1 U5.L5), TESTPOINTS (ADC.1)
AD9363_AUXDAC1: AD9363 (C206.1 U5.B3), TESTPOINTS (DAC1.1), AD9363 OSCILLATORS (R5.1)
AD9363_AUXDAC2: AD9363 (C208.1 U5.C3), TESTPOINTS (DAC2.1)
AD9363_GPO_0: AD9363 (U5.B7), TESTPOINTS (GPO0.1)
AD9363_GPO_1: AD9363 (U5.B6), TESTPOINTS (GPO1.1)
AD9363_GPO_2: AD9363 (U5.B5), TESTPOINTS (GPO2.1)
AD9363_GPO_3: AD9363 (U5.B4), TESTPOINTS (GPO3.1)
CTRL_IN0: ZYNQ 34_35 and QPSI (U4.F13), AD9363 (U5.C5)
CTRL_IN1: ZYNQ 34_35 and QPSI (U4.F14), AD9363 (U5.C6)
CTRL_IN2: ZYNQ 34_35 and QPSI (U4.G15), AD9363 (U5.D6)
CTRL_IN3: ZYNQ 34_35 and QPSI (U4.F15), AD9363 (U5.D5)
IO_02_34_AD9361_CLKOUT: ZYNQ 34_35 and QPSI (U4.P8), AD9363 (U5.J6)
IO_02_34_AD9361_RST: ZYNQ 34_35 and QPSI (U4.P9), AD9363 (U5.K5)
IO_L01_34_FB_CLK: ZYNQ 34_35 and QPSI (U4.P10), AD9363 (U5.F10)
IO_L01_34_RX_D0: ZYNQ 34_35 and QPSI (U4.H14), AD9363 (U5.K11)
IO_L01_34_RX_D1: ZYNQ 34_35 and QPSI (U4.J13), AD9363 (U5.J12)
IO_L02_34_RX_D2: ZYNQ 34_35 and QPSI (U4.G14), AD9363 (U5.K10)
IO_L02_34_RX_D3: ZYNQ 34_35 and QPSI (U4.H13), AD9363 (U5.J11)
IO_L03_34_RX_D4: ZYNQ 34_35 and QPSI (U4.G12), AD9363 (U5.K9)
IO_L03_34_RX_D5: ZYNQ 34_35 and QPSI (U4.H12), AD9363 (U5.J10)
IO_L04_34_RX_D6: ZYNQ 34_35 and QPSI (U4.G11), AD9363 (U5.K8)
IO_L04_34_RX_D7: ZYNQ 34_35 and QPSI (U4.J14), AD9363 (U5.J9)
IO_L05_34_RX_D8: ZYNQ 34_35 and QPSI (U4.J15), AD9363 (U5.K7)
IO_L05_34_RX_D9: ZYNQ 34_35 and QPSI (U4.K15), AD9363 (U5.J8)
IO_L06_34_RX_D10: ZYNQ 34_35 and QPSI (U4.H11), AD9363 (U5.J7)
IO_L06_34_RX_D11: ZYNQ 34_35 and QPSI (U4.J11), AD9363 (U5.H8)
IO_L07_34_RX_FRAME: ZYNQ 34_35 and QPSI (U4.N13), AD9363 (U5.G8)
IO_L08_34_CTRL_OUT0: ZYNQ 34_35 and QPSI (U4.L15), AD9363 (U5.D4)
IO_L08_34_CTRL_OUT1: ZYNQ 34_35 and QPSI (U4.M15), AD9363 (U5.E4)
IO_L09_34_TX_FRAME: ZYNQ 34_35 and QPSI (U4.L14), AD9363 (U5.G9)
IO_L10_34_EN_AGC: ZYNQ 34_35 and QPSI (U4.L13), AD9363 (U5.G5)
IO_L11_34_ENABLE: ZYNQ 34_35 and QPSI (U4.K12), AD9363 (U5.G6)
IO_L11_34_TXNRX: ZYNQ 34_35 and QPSI (U4.K11), AD9363 (U5.H4)
IO_L12_MRCC_34_DATA_CLK: ZYNQ 34_35 and QPSI (U4.L12), AD9363 (U5.G11)
IO_L13_34_CTRL_OUT2: ZYNQ 34_35 and QPSI (U4.N11), AD9363 (U5.E5)
IO_L13_34_CTRL_OUT3: ZYNQ 34_35 and QPSI (U4.N12), AD9363 (U5.E6)
IO_L15_34_TX_D0: ZYNQ 34_35 and QPSI (U4.P15), AD9363 (U5.E12)
IO_L15_34_TX_D1: ZYNQ 34_35 and QPSI (U4.R13), AD9363 (U5.D11)
IO_L16_34_TX_D2: ZYNQ 34_35 and QPSI (U4.R15), AD9363 (U5.E11)
IO_L16_34_TX_D3: ZYNQ 34_35 and QPSI (U4.P11), AD9363 (U5.D10)
IO_L17_34_TX_D4: ZYNQ 34_35 and QPSI (U4.R11), AD9363 (U5.E10)
IO_L17_34_TX_D5: ZYNQ 34_35 and QPSI (U4.R12), AD9363 (U5.D9)
IO_L18_34_TX_D6: ZYNQ 34_35 and QPSI (U4.P14), AD9363 (U5.E9)
IO_L18_34_TX_D7: ZYNQ 34_35 and QPSI (U4.P13), AD9363 (U5.D8)
IO_L19_34_TX_D8: ZYNQ 34_35 and QPSI (U4.N9), AD9363 (U5.E8)
IO_L19_34_TX_D9: ZYNQ 34_35 and QPSI (U4.M9), AD9363 (U5.D7)
IO_L20_34_TX_D10: ZYNQ 34_35 and QPSI (U4.R8), AD9363 (U5.F8)
IO_L20_34_TX_D11: ZYNQ 34_35 and QPSI (U4.R7), AD9363 (U5.E7)
IO_L21_34_CTRL_OUT4: ZYNQ 34_35 and QPSI (U4.M10), AD9363 (U5.F6)
IO_L21_34_CTRL_OUT5: ZYNQ 34_35 and QPSI (U4.M11), AD9363 (U5.F5)
IO_L22_34_CTRL_OUT6: ZYNQ 34_35 and QPSI (U4.N7), AD9363 (U5.F4)
IO_L22_34_CTRL_OUT7: ZYNQ 34_35 and QPSI (U4.N8), AD9363 (U5.G4)
IO_L23_35_SPI_CLK: ZYNQ 34_35 and QPSI (U4.E11), AD9363 (U5.J4)
IO_L23_35_SPI_ENB: ZYNQ 34_35 and QPSI (U4.E12), AD9363 (U5.K6)
IO_L24_35_SPI_DI: ZYNQ 34_35 and QPSI (U4.E13), AD9363 (U5.J5)
IO_L24_35_SPI_DO: ZYNQ 34_35 and QPSI (U4.F12), AD9363 (U5.L6)
JTAG_TCK: ZYNQ JTAG and Decoupling (U4.G9), CONNECTORS_SELECTORS (P1.4), TESTPOINTS (TCK.1)
JTAG_TDI: ZYNQ JTAG and Decoupling (U4.L7), CONNECTORS_SELECTORS (P1.8), TESTPOINTS (TDI.1)
JTAG_TDO: ZYNQ JTAG and Decoupling (U4.L8), CONNECTORS_SELECTORS (P1.6), TESTPOINTS (TDO.1)
JTAG_TMS: ZYNQ JTAG and Decoupling (U4.L9), CONNECTORS_SELECTORS (P1.2), TESTPOINTS (TMS.1)
PG_1P3V: USB (R13.2), POWERMANAGE (U1.5 U7.5), POWERMANAGE2 (U11.4 U12.4), TESTPOINTS (PG_1P3V.1)
PG_1P35V: POWERREG (R50.1 R50.2 U6.12), POWERMANAGE (U1.4 U7.4)
PL_GPIO0: ZYNQ 34_35 and QPSI (U4.K13), TESTPOINTS (L10P.1)
PL_GPIO1: ZYNQ 34_35 and QPSI (U4.M12), TESTPOINTS (L12N.1)
PL_GPIO2: ZYNQ 34_35 and QPSI (U4.R10), TESTPOINTS (L24N.1)
PL_GPIO3: ZYNQ 34_35 and QPSI (R97.1 U4.N14), TESTPOINTS (L7N.1)
PL_GPIO4: ZYNQ 34_35 and QPSI (R68.1 U4.M14), TESTPOINTS (L9N.1)
PS-SRST#: USB (R74.1 U4.B11), ZYNQ 34_35 and QPSI (U13.A4)
PS_GPIO0: USB (U4.D8), TESTPOINTS (MIO0.1)
PS_GPIO1: USB (U4.B10), TESTPOINTS (MIO10.1)
PS_GPIO2: USB (U4.D6), TESTPOINTS (MIO11.1)
PS_GPIO3: USB (U4.B5), TESTPOINTS (MIO09.1)
PS_GPIO4: USB (U4.C13), TESTPOINTS (MIO53.1)
PS_GPIO5: USB (U4.D13), TESTPOINTS (MIO49.1)
PS_GPIO6: USB (U4.B12), TESTPOINTS (MIO48.1), AD9363 OSCILLATORS (R102.1)
PS_MIO01_500_QSPI0_SS_B: USB (U4.A5), ZYNQ 34_35 and QPSI (R14.2 U13.C2)
PS_MIO02_500_QSPI0_IO0: USB (U4.A8), ZYNQ 34_35 and QPSI (R120.1 U13.D3)
PS_MIO03_500_QSPI0_IO1: USB (U4.A7), ZYNQ 34_35 and QPSI (R119.1 U13.D2)
PS_MIO04_500_QSPI0_IO2: USB (U4.C8), ZYNQ 34_35 and QPSI (R121.1 U13.C4)
PS_MIO05_500_QSPI0_IO3: USB (U4.A9), ZYNQ 34_35 and QPSI (R122.1 U13.D4), CONNECTORS_SELECTORS (P1.5), TESTPOINTS (JTAG_BOOT.1)
PS_MIO06_500_QSPI0_SCLK: USB (U4.A10), ZYNQ 34_35 and QPSI (R116.1 U13.B2)
PWR_CLK: POWERREG (R89.2 R90.1), POWERMANAGE (U3.1)
RX1A_N: AD9363 (U5.M2), RF FRONTEND (C133.2)
RX1A_P: AD9363 (U5.M1), RF FRONTEND (C134.2)
RX2A_N: AD9363 (U5.A1), RF FRONTEND (C175.2 R69.1)
RX2A_P: AD9363 (U5.A2), RF FRONTEND (C176.2 R104.1)
TX1A_N: AD9363 (U5.M8), RF FRONTEND (C131.1 L8.1)
TX1A_P: AD9363 (U5.M7), RF FRONTEND (C132.1 L9.1)
TX2A_N: AD9363 (U5.A7), RF FRONTEND (C130.1 L1.1)
TX2A_P: AD9363 (U5.A8), RF FRONTEND (C156.1 L7.1)
UART_RX: USB (R95.2 U4.C6), CONNECTORS_SELECTORS (P1.1), TESTPOINTS (RX.1)
UART_TX: USB (U4.B7 U9.2), CONNECTORS_SELECTORS (P1.3), TESTPOINTS (TX.1)
USB_ID: USB (U15.23), CONNECTORS_SELECTORS (D1.3 P2.4)
USB_OTG_CPEN: USB (U15.17), CONNECTORS_SELECTORS (U16.B1)
USB_OTG_N: USB (U15.19), CONNECTORS_SELECTORS (L6.4)
USB_OTG_P: USB (U15.18), CONNECTORS_SELECTORS (L6.1)
USB_UART_N: USB (C196.1 R79.2), CONNECTORS_SELECTORS (D2.6 P3.2)
USB_UART_P: USB (C197.1 R81.1), CONNECTORS_SELECTORS (D2.1 P3.3)
USB_VBUS_OTG: USB (U15.22), CONNECTORS_SELECTORS (R88.2)
USR_LED: USB (U4.D10), ZYNQ JTAG and Decoupling (Q4.1 R75.1)
VCCPINT: ZYNQ JTAG and Decoupling (17 pins), POWERMANAGE (6 pins), TESTPOINTS (1P0V.1)
VDD_INTERFACE: AD9363 (U5.H12), POWERMANAGE (7 pins)
VIN: USB (5 pins), DDR3 (C62.1 R221.1 R222.1 U14.10), ZYNQ JTAG and Decoupling (DS1.1 DS2.1), CONNECTORS_SELECTORS (C184.1 C185.1 U8.9-10 U8.15-16), POWERREG (12 pins), POWERMANAGE (C8.1 C9.1 C11.1 R1.2), POWERMANAGE2 (C123.1 C169.1 E2.1 E7.1)
VIN_5V_USB_POWER: USB (R80.1), CONNECTORS_SELECTORS (7 pins)
VTTVREF: DDR3 (7 pins), ZYNQ JTAG and Decoupling (U4.F4)
XTALN: AD9363 (U5.M12), AD9363 OSCILLATORS (C157.1 C204.2)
